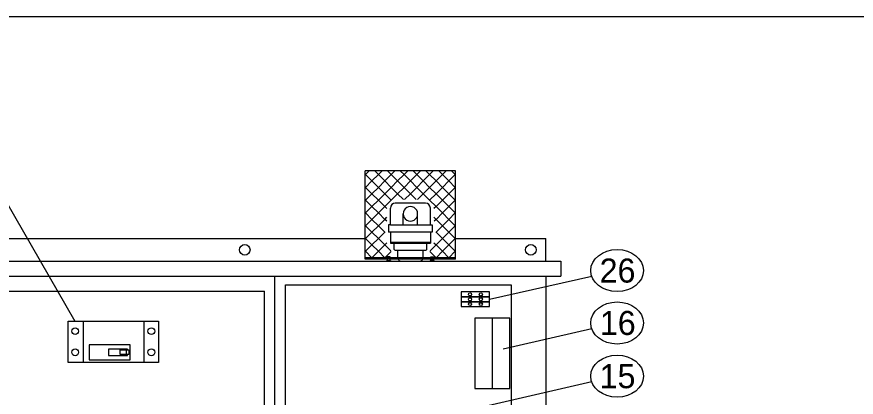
# Model space of a CAD drawing. Extents: x 99862 to 103680, y 99470 to 105076.
# Drawn here: x 102025 to 102583, y 104822 to 105076 of the extents above; entities that cross this region are included whole.
import ezdxf

# ---------------------------------------------------------------- set-up
doc = ezdxf.new("R2010")
doc.units = 0
for name, color, linetype in [('Level 1', 7, 'Continuous'), ('Level 15', 7, 'Continuous'), ('Level 20', 7, 'Continuous'), ('Level 40', 7, 'Continuous')]:
    doc.layers.add(name, color=color, linetype=linetype)

msp = doc.modelspace()

# ---------------------------------------------------------------- linework, layer by layer
at = {"layer": 'Level 1'}
for p, q in [((102256.66, 104915.18), (102256.66, 104972.94)), ((102316.66, 104972.94), (102256.66, 104972.94)), ((102256.88, 104970.49), (102259.34, 104972.94)), ((102262.94, 104972.94), (102265.39, 104970.49)), ((102267.84, 104972.94), (102265.39, 104970.49)), ((102273.9, 104970.49), (102271.45, 104972.94)), ((102276.35, 104972.94), (102273.9, 104970.49)), ((102282.41, 104970.49), (102279.96, 104972.94)), ((102284.86, 104972.94), (102282.41, 104970.49)), ((102290.92, 104970.49), (102288.46, 104972.94)), ((102293.37, 104972.94), (102290.92, 104970.49)), ((102299.42, 104970.49), (102296.97, 104972.94)), ((102301.88, 104972.94), (102299.42, 104970.49)), ((102305.48, 104972.94), (102307.93, 104970.49)), ((102307.93, 104970.49), (102310.39, 104972.94)), ((102316.44, 104970.49), (102313.99, 104972.94)), ((102316.66, 104915.18), (102316.66, 104972.94)), ((102256.66, 104970.71), (102256.88, 104970.49)), ((102256.88, 104970.49), (102256.66, 104970.26)), ((102261.14, 104966.23), (102256.88, 104970.49)), ((102256.88, 104961.98), (102261.14, 104966.23)), ((102265.39, 104970.49), (102261.14, 104966.23)), ((102261.14, 104966.23), (102265.39, 104961.98)), ((102265.39, 104970.49), (102269.65, 104966.23)), ((102269.65, 104966.23), (102265.39, 104961.98)), ((102269.65, 104966.23), (102273.9, 104970.49)), ((102273.9, 104961.98), (102269.65, 104966.23)), ((102273.9, 104970.49), (102278.15, 104966.23)), ((102278.15, 104966.23), (102273.9, 104961.98)), ((102278.15, 104966.23), (102282.41, 104970.49)), ((102282.41, 104961.98), (102278.15, 104966.23)), ((102282.41, 104970.49), (102286.66, 104966.23)), ((102286.66, 104966.23), (102282.41, 104961.98)), ((102286.66, 104966.23), (102290.92, 104970.49)), ((102290.92, 104961.98), (102286.66, 104966.23)), ((102290.92, 104970.49), (102295.17, 104966.23)), ((102295.17, 104966.23), (102290.92, 104961.98)), ((102295.17, 104966.23), (102299.42, 104970.49)), ((102299.42, 104961.98), (102295.17, 104966.23)), ((102299.42, 104970.49), (102303.68, 104966.23)), ((102303.68, 104966.23), (102299.42, 104961.98)), ((102303.68, 104966.23), (102307.93, 104970.49)), ((102307.93, 104961.98), (102303.68, 104966.23)), ((102307.93, 104970.49), (102312.19, 104966.23)), ((102312.19, 104966.23), (102307.93, 104961.98)), ((102312.19, 104966.23), (102316.44, 104970.49)), ((102316.44, 104961.98), (102312.19, 104966.23)), ((102316.66, 104970.71), (102316.44, 104970.49)), ((102316.44, 104970.49), (102316.66, 104970.27)), ((102256.66, 104962.2), (102256.88, 104961.98)), ((102256.88, 104961.98), (102256.66, 104961.76)), ((102261.14, 104957.72), (102256.88, 104961.98)), ((102265.39, 104961.98), (102261.14, 104957.72)), ((102265.39, 104961.98), (102269.65, 104957.72)), ((102269.65, 104957.72), (102273.9, 104961.98)), ((102273.9, 104961.98), (102278.15, 104957.72)), ((102278.15, 104957.72), (102282.41, 104961.98)), ((102282.41, 104961.98), (102286.66, 104957.72)), ((102286.66, 104957.72), (102290.92, 104961.98)), ((102290.92, 104961.98), (102295.17, 104957.72)), ((102295.17, 104957.72), (102299.42, 104961.98)), ((102299.42, 104961.98), (102303.68, 104957.72)), ((102303.68, 104957.72), (102307.93, 104961.98)), ((102307.93, 104961.98), (102312.19, 104957.72)), ((102312.19, 104957.72), (102316.44, 104961.98)), ((102316.66, 104962.2), (102316.44, 104961.98)), ((102316.44, 104961.98), (102316.66, 104961.76)), ((102256.88, 104953.47), (102261.14, 104957.72)), ((102261.14, 104957.72), (102265.39, 104953.47)), ((102269.65, 104957.72), (102265.39, 104953.47)), ((102273.9, 104953.47), (102269.65, 104957.72)), ((102278.15, 104957.72), (102273.9, 104953.47)), ((102282.03, 104953.85), (102278.15, 104957.72)), ((102286.66, 104957.72), (102282.79, 104953.85)), ((102290.54, 104953.85), (102286.66, 104957.72)), ((102295.17, 104957.72), (102291.3, 104953.85)), ((102299.42, 104953.47), (102295.17, 104957.72)), ((102303.68, 104957.72), (102299.42, 104953.47)), ((102307.93, 104953.47), (102303.68, 104957.72)), ((102312.19, 104957.72), (102307.93, 104953.47)), ((102316.44, 104953.47), (102312.19, 104957.72)), ((102256.66, 104953.69), (102256.88, 104953.47)), ((102256.88, 104953.47), (102256.66, 104953.25)), ((102261.14, 104949.22), (102256.88, 104953.47)), ((102256.88, 104944.96), (102261.14, 104949.22)), ((102265.39, 104953.47), (102261.14, 104949.22)), ((102261.14, 104949.22), (102265.39, 104944.96)), ((102265.39, 104953.47), (102269.65, 104949.22)), ((102269.65, 104949.22), (102265.39, 104944.96)), ((102269.65, 104949.22), (102273.9, 104953.47)), ((102271.02, 104947.84), (102269.65, 104949.22)), ((102273.9, 104953.47), (102274.12, 104953.25)), ((102296.69, 104951.44), (102276.63, 104951.44)), ((102299.21, 104953.25), (102299.42, 104953.47)), ((102299.42, 104953.47), (102303.68, 104949.22)), ((102303.68, 104949.22), (102302.3, 104947.84)), ((102303.68, 104949.22), (102307.93, 104953.47)), ((102307.93, 104944.96), (102303.68, 104949.22)), ((102307.93, 104953.47), (102312.19, 104949.22)), ((102312.19, 104949.22), (102307.93, 104944.96)), ((102312.19, 104949.22), (102316.44, 104953.47)), ((102316.44, 104944.96), (102312.19, 104949.22)), ((102316.66, 104953.69), (102316.44, 104953.47)), ((102316.44, 104953.47), (102316.66, 104953.25)), ((102256.66, 104945.18), (102256.88, 104944.96)), ((102256.88, 104944.96), (102256.66, 104944.74)), ((102261.14, 104940.71), (102256.88, 104944.96)), ((102265.39, 104944.96), (102261.14, 104940.71)), ((102265.39, 104944.96), (102269.65, 104940.71)), ((102273.43, 104937), (102273.43, 104948.23)), ((102281.85, 104937), (102281.85, 104944.38)), ((102291.47, 104937), (102291.47, 104944.38)), ((102299.9, 104937), (102299.9, 104948.23)), ((102303.68, 104940.71), (102307.93, 104944.96)), ((102307.93, 104944.96), (102312.19, 104940.71)), ((102312.19, 104940.71), (102316.44, 104944.96)), ((102316.66, 104945.18), (102316.44, 104944.96)), ((102316.44, 104944.96), (102316.66, 104944.74)), ((102256.88, 104936.45), (102261.14, 104940.71)), ((102261.14, 104940.71), (102265.39, 104936.45)), ((102269.65, 104940.71), (102265.39, 104936.45)), ((102269.65, 104940.71), (102271.02, 104942.08)), ((102270.94, 104939.41), (102269.65, 104940.71)), ((102302.3, 104942.08), (102303.68, 104940.71)), ((102303.68, 104940.71), (102302.38, 104939.41)), ((102307.93, 104936.45), (102303.68, 104940.71)), ((102312.19, 104940.71), (102307.93, 104936.45)), ((102316.44, 104936.45), (102312.19, 104940.71)), ((102256.66, 104936.67), (102256.88, 104936.45)), ((102256.88, 104936.45), (102256.66, 104936.23)), ((102261.14, 104932.2), (102256.88, 104936.45)), ((102256.88, 104927.94), (102261.14, 104932.2)), ((102265.39, 104936.45), (102261.14, 104932.2)), ((102261.14, 104932.2), (102265.39, 104927.94)), ((102265.39, 104936.45), (102269.65, 104932.2)), ((102269.65, 104932.2), (102265.39, 104927.94)), ((102269.65, 104932.2), (102269.82, 104932.37)), ((102269.82, 104932.03), (102269.65, 104932.2)), ((102273.43, 104937), (102272.22, 104937)), ((102272.22, 104937), (102272.22, 104932.19)), ((102301.1, 104932.19), (102272.22, 104932.19)), ((102273.43, 104937), (102299.9, 104937)), ((102273.43, 104932.19), (102273.43, 104924.97)), ((102299.9, 104937), (102301.1, 104937)), ((102299.9, 104932.19), (102299.9, 104924.97)), ((102301.1, 104937), (102301.1, 104932.19)), ((102303.51, 104932.37), (102303.68, 104932.2)), ((102303.68, 104932.2), (102303.51, 104932.03)), ((102303.68, 104932.2), (102307.93, 104936.45)), ((102307.93, 104927.94), (102303.68, 104932.2)), ((102307.93, 104936.45), (102312.19, 104932.2)), ((102312.19, 104932.2), (102307.93, 104927.94)), ((102312.19, 104932.2), (102316.44, 104936.45)), ((102316.44, 104927.94), (102312.19, 104932.2)), ((102316.66, 104936.67), (102316.44, 104936.45)), ((102316.44, 104936.45), (102316.66, 104936.23)), ((102256.66, 104928.17), (102256.88, 104927.94)), ((102256.88, 104927.94), (102256.66, 104927.72)), ((102261.14, 104923.69), (102256.88, 104927.94)), ((102265.39, 104927.94), (102261.14, 104923.69)), ((102265.39, 104927.94), (102269.65, 104923.69)), ((102303.68, 104923.69), (102307.93, 104927.94)), ((102307.93, 104927.94), (102312.19, 104923.69)), ((102312.19, 104923.69), (102316.44, 104927.94)), ((102316.66, 104928.16), (102316.44, 104927.94)), ((102316.44, 104927.94), (102316.66, 104927.72)), ((102256.88, 104919.44), (102261.14, 104923.69)), ((102261.14, 104923.69), (102265.39, 104919.44)), ((102269.65, 104923.69), (102265.39, 104919.44)), ((102269.65, 104923.69), (102271.02, 104925.06)), ((102273.61, 104919.73), (102269.65, 104923.69)), ((102273.43, 104925.57), (102299.9, 104925.57)), ((102273.43, 104924.97), (102299.9, 104924.97)), ((102275.83, 104920.76), (102275.83, 104924.97)), ((102297.49, 104920.76), (102297.49, 104924.97)), ((102303.68, 104923.69), (102299.71, 104919.73)), ((102302.3, 104925.07), (102303.68, 104923.69)), ((102307.93, 104919.44), (102303.68, 104923.69)), ((102312.19, 104923.69), (102307.93, 104919.44)), ((102316.44, 104919.44), (102312.19, 104923.69)), ((102256.66, 104919.66), (102256.88, 104919.44)), ((102256.88, 104919.44), (102256.66, 104919.21)), ((102261.14, 104915.18), (102256.88, 104919.44)), ((102265.39, 104919.44), (102261.14, 104915.18)), ((102265.39, 104919.44), (102269.65, 104915.18)), ((102269.65, 104915.18), (102273.79, 104919.33)), ((102276.43, 104920.16), (102296.89, 104920.16)), ((102278.24, 104915.35), (102278.24, 104920.16)), ((102295.08, 104915.35), (102295.08, 104920.16)), ((102299.53, 104919.33), (102303.68, 104915.18)), ((102303.68, 104915.18), (102307.93, 104919.44)), ((102307.93, 104919.44), (102312.19, 104915.18)), ((102312.19, 104915.18), (102316.44, 104919.44)), ((102316.66, 104919.66), (102316.44, 104919.44)), ((102316.44, 104919.44), (102316.66, 104919.22)), ((102316.66, 104915.18), (102256.66, 104915.18)), ((102256.66, 104914.14), (102256.66, 104915.08)), ((102316.66, 104915.08), (102256.66, 104915.08)), ((102316.66, 104914.14), (102256.66, 104914.14)), ((102280.65, 104912.94), (102292.68, 104912.94)), ((102316.66, 104914.14), (102316.66, 104915.08)), ((102203.66, 104897.04), (102353.66, 104897.04)), ((102203.66, 104537.04), (102203.66, 104897.04)), ((102353.66, 104897.04), (102353.66, 104537.04)), ((102189.66, 104518.01), (102189.66, 104892.87)), ((102097.8, 104853.79), (102097.8, 104850.73))]:
    msp.add_line(p, q, dxfattribs=at)
for points in [[(99862, 102999.5), (103151, 102999.5), (103151, 105075.5), (99862, 105075.5)], [(102320.45, 104889.16), (102339.23, 104889.16), (102339.23, 104892.39), (102320.45, 104892.39)], [(102320.45, 104885.93), (102339.23, 104885.93), (102339.23, 104889.16), (102320.45, 104889.16)], [(102320.45, 104882.7), (102339.23, 104882.7), (102339.23, 104885.93), (102320.45, 104885.93)], [(102059.29, 104873.04), (102119.29, 104873.04), (102119.29, 104845.54), (102059.29, 104845.54)], [(102069.6, 104873.04), (102109.6, 104873.04), (102109.6, 104845.54), (102069.6, 104845.54)], [(102073.35, 104847.26), (102100.54, 104847.26), (102100.54, 104857.26), (102073.35, 104857.26)], [(102099.56, 104850.73), (102093.81, 104850.73), (102093.81, 104853.79), (102099.56, 104853.79)]]:
    msp.add_lwpolyline(points, close=True, dxfattribs=at)
msp.add_lwpolyline([(102098.67, 104853.79), (102098.67, 104854.34), (102086.08, 104854.34), (102086.08, 104850.18), (102098.67, 104850.18), (102098.67, 104850.73)], dxfattribs=at)
for centre, radius in [((102326.26, 104890.77), 1.03), ((102326.26, 104887.55), 1.03), ((102333.41, 104890.77), 1.03), ((102333.41, 104887.55), 1.03), ((102326.26, 104884.32), 1.03), ((102333.41, 104884.32), 1.03), ((102063.98, 104866.32), 2.25), ((102114.6, 104866.32), 2.25), ((102063.98, 104852.26), 2.25), ((102114.6, 104852.26), 2.25)]:
    msp.add_circle(centre, radius, dxfattribs=at)
for centre, radius, start, end in [((102276.63, 104948.23), 3.21, 90, 180), ((102286.66, 104944.38), 4.81, 359.9997, 180), ((102296.69, 104948.23), 3.21, 0, 90), ((102286.66, 104944.38), 4.81, 180, 0.0003), ((102276.43, 104920.76), 0.602, 180, 270), ((102280.65, 104915.35), 2.41, 180, 270), ((102292.68, 104915.35), 2.41, 270, 0), ((102296.89, 104920.76), 0.602, 270, 0)]:
    msp.add_arc(centre, radius, start, end, dxfattribs=at)
at = {"layer": 'Level 15'}
for p, q in [((102017.7, 104953.33), (102063.81, 104873.04)), ((101976.66, 104902.94), (102376.66, 104902.94)), ((102339.23, 104887.55), (102407.13, 104902.84)), ((102407.16, 104867.93), (102348.18, 104854.42)), ((102407.16, 104832.53), (102326.66, 104814.08))]:
    msp.add_line(p, q, dxfattribs=at)
for centre in [(102176.66, 104920.44), (102366.66, 104920.44)]:
    msp.add_circle(centre, 3.5, dxfattribs=at)
at = {"layer": 'Level 20'}
for centre in [(102423.98, 104906.64), (102423.98, 104871.78), (102423.98, 104836.38)]:
    msp.add_ellipse(centre, major_axis=(-17.5, 0), ratio=0.8, dxfattribs=at)
at = {"layer": 'Level 40'}
for p, q in [((101976.66, 104927.94), (102256.66, 104927.94)), ((102316.66, 104927.94), (102376.66, 104927.94)), ((102376.66, 104912.94), (102376.66, 104927.94)), ((101976.66, 104912.94), (102376.66, 104912.94)), ((102376.66, 104912.94), (102386.66, 104912.94)), ((102386.66, 104912.94), (102386.66, 104902.94)), ((102196.66, 104512.94), (102196.66, 104902.94)), ((102376.66, 104902.94), (102376.66, 104497.94)), ((102376.66, 104902.94), (102386.66, 104902.94)), ((101983.66, 104892.87), (102189.66, 104892.87)), ((102341.08, 104874.88), (102341.08, 104828.25))]:
    msp.add_line(p, q, dxfattribs=at)
for points in [[(102273.21, 104915.1), (102273.21, 104915.88), (102271.24, 104915.88), (102271.24, 104915.1)], [(102300.12, 104915.1), (102300.12, 104915.88), (102302.08, 104915.88), (102302.08, 104915.1)], [(102273.57, 104913.18), (102273.57, 104912.94), (102270.88, 104912.94), (102270.88, 104913.18)], [(102273.54, 104913.35), (102273.54, 104913.18), (102270.91, 104913.18), (102270.91, 104913.35)], [(102273.21, 104913.35), (102273.21, 104914.14), (102271.24, 104914.14), (102271.24, 104913.35)], [(102299.76, 104913.18), (102299.76, 104912.94), (102302.44, 104912.94), (102302.44, 104913.18)], [(102299.79, 104913.35), (102299.79, 104913.18), (102302.41, 104913.18), (102302.41, 104913.35)], [(102300.12, 104913.35), (102300.12, 104914.14), (102302.08, 104914.14), (102302.08, 104913.35)], [(102329.42, 104874.88), (102329.42, 104828.25), (102352.74, 104828.25), (102352.74, 104874.88)]]:
    msp.add_lwpolyline(points, close=True, dxfattribs=at)

# ---------------------------------------------------------------- texts
at = {"layer": 'Level 20'}
for s, p in [('26', (102412.35, 104898.64)), ('16', (102412.5, 104863.78)), ('15', (102412.35, 104828.38))]:
    msp.add_text(s, height=16, dxfattribs=at).set_placement(p)

doc.saveas('drawing.dxf')
